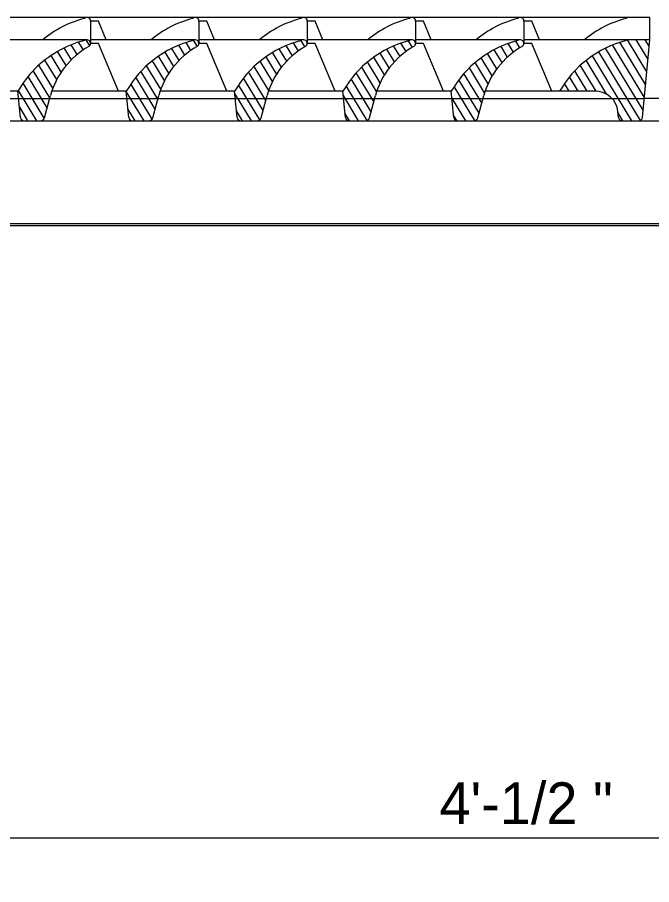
# Model space of a CAD drawing. Extents: x 0.9 to 8.1, y 0.4 to 10.5.
# Drawn here: x 1.927 to 2.656, y 6.36 to 7.357 of the extents above; entities that cross this region are included whole.
import ezdxf

# ---------------------------------------------------------------- set-up
doc = ezdxf.new("R2010")
doc.units = 0
for name, color, linetype in [('DETL-DIMS', 7, 'Continuous'), ('DETL-LINE', 7, 'Continuous'), ('DETL-NOTE', 7, 'Continuous')]:
    doc.layers.add(name, color=color, linetype=linetype)

msp = doc.modelspace()

# ---------------------------------------------------------------- linework, layer by layer
at = {"layer": 'DETL-DIMS'}
msp.add_line((1.8254, 6.41382), (3.48103, 6.41382), dxfattribs=at)
at = {"layer": 'DETL-LINE'}
for p, q in [((2.62959, 7.35673), (1.88268, 7.35673)), ((2.0205, 7.35249), (2.01161, 7.35249)), ((2.01161, 7.35249), (2.01161, 7.32709)), ((2.02944, 7.33132), (2.0205, 7.35249)), ((2.14499, 7.35249), (2.13609, 7.35249)), ((2.13609, 7.35249), (2.13609, 7.32709)), ((2.15392, 7.33132), (2.14499, 7.35249)), ((2.26947, 7.35249), (2.26058, 7.35249)), ((2.26058, 7.35249), (2.26058, 7.32709)), ((2.27841, 7.33132), (2.26947, 7.35249)), ((2.39396, 7.35249), (2.38506, 7.35249)), ((2.38506, 7.35249), (2.38506, 7.32709)), ((2.40289, 7.33132), (2.39396, 7.35249)), ((2.51844, 7.35249), (2.50955, 7.35249)), ((2.50955, 7.35249), (2.50955, 7.32709)), ((2.52737, 7.33132), (2.51844, 7.35249)), ((2.65404, 7.35673), (2.62959, 7.35673)), ((2.65404, 7.33132), (2.65404, 7.35673)), ((2.00716, 7.33132), (1.88713, 7.33132)), ((2.01058, 7.32438), (2.00641, 7.33126)), ((2.13165, 7.33132), (2.01161, 7.33132)), ((2.13423, 7.32364), (2.12981, 7.33094)), ((2.25613, 7.33132), (2.13609, 7.33132)), ((2.25778, 7.32308), (2.25335, 7.33039)), ((2.38062, 7.33132), (2.26058, 7.33132)), ((2.38132, 7.32252), (2.37674, 7.33009)), ((2.5051, 7.33132), (2.38506, 7.33132)), ((2.50488, 7.32196), (2.50013, 7.32978)), ((2.62959, 7.33132), (2.50955, 7.33132)), ((2.65065, 7.29446), (2.6284, 7.33117)), ((2.65404, 7.33132), (2.62959, 7.33132)), ((2.652, 7.30917), (2.63858, 7.33132)), ((2.64583, 7.242), (2.65404, 7.33132)), ((2.65336, 7.32388), (2.64885, 7.33132)), ((1.98954, 7.30827), (1.98133, 7.32181)), ((1.99617, 7.31426), (1.98942, 7.3254)), ((2.00323, 7.31955), (1.99784, 7.32846)), ((2.0205, 7.32709), (2.01161, 7.32709)), ((2.04373, 7.27204), (2.0205, 7.32709)), ((2.11323, 7.30747), (2.10484, 7.32132)), ((2.11981, 7.31356), (2.11288, 7.32498)), ((2.12682, 7.31893), (2.12126, 7.32811)), ((2.14499, 7.32709), (2.13609, 7.32709)), ((2.16822, 7.27204), (2.14499, 7.32709)), ((2.23693, 7.30666), (2.22834, 7.32083)), ((2.24345, 7.31284), (2.23635, 7.32456)), ((2.25041, 7.3183), (2.24468, 7.32775)), ((2.26947, 7.32709), (2.26058, 7.32709)), ((2.2927, 7.27204), (2.26947, 7.32709)), ((2.36064, 7.30584), (2.35185, 7.32033)), ((2.3671, 7.31211), (2.35982, 7.32412)), ((2.37401, 7.31766), (2.36811, 7.32738)), ((2.39396, 7.32709), (2.38506, 7.32709)), ((2.41718, 7.27204), (2.39396, 7.32709)), ((2.48435, 7.30501), (2.47537, 7.31982)), ((2.49076, 7.31137), (2.4833, 7.32368)), ((2.49761, 7.31701), (2.49155, 7.327)), ((2.51844, 7.32709), (2.50955, 7.32709)), ((2.54167, 7.27204), (2.51844, 7.32709)), ((2.6466, 7.25034), (2.60339, 7.32163)), ((2.64795, 7.26505), (2.61146, 7.32524)), ((2.6493, 7.27976), (2.61986, 7.32833)), ((1.9777, 7.29393), (1.96611, 7.31304)), ((1.98337, 7.30151), (1.97356, 7.31769)), ((2.10152, 7.29292), (2.08969, 7.31243)), ((2.10712, 7.30062), (2.0971, 7.31714)), ((2.22535, 7.2919), (2.21328, 7.3118)), ((2.23088, 7.29971), (2.22065, 7.31658)), ((2.34918, 7.29086), (2.33687, 7.31117)), ((2.35464, 7.29879), (2.3442, 7.31602)), ((2.47303, 7.28981), (2.46046, 7.31053)), ((2.47842, 7.29785), (2.46776, 7.31544)), ((2.63346, 7.23815), (2.58819, 7.31281)), ((2.64345, 7.23861), (2.59563, 7.31748)), ((1.96823, 7.27568), (1.95218, 7.30214)), ((1.97261, 7.28538), (1.95898, 7.30787)), ((2.09223, 7.27437), (2.07585, 7.30139)), ((2.09651, 7.28424), (2.0826, 7.30718)), ((2.21624, 7.27305), (2.19952, 7.30063)), ((2.22042, 7.28309), (2.20623, 7.3065)), ((2.34027, 7.27169), (2.32319, 7.29987)), ((2.34434, 7.28191), (2.32986, 7.3058)), ((2.46431, 7.27032), (2.44687, 7.29909)), ((2.46827, 7.28072), (2.4535, 7.30509)), ((2.59238, 7.27204), (2.5743, 7.30186)), ((2.60488, 7.26835), (2.58108, 7.30761)), ((1.96473, 7.26451), (1.94573, 7.29585)), ((2.08882, 7.26306), (2.06944, 7.29503)), ((2.21291, 7.2616), (2.19315, 7.29419)), ((2.337, 7.26015), (2.31687, 7.29335)), ((2.46109, 7.2587), (2.4406, 7.2925)), ((2.58209, 7.27207), (2.56786, 7.29554)), ((1.95837, 7.24113), (1.93397, 7.28139)), ((1.96155, 7.25282), (1.93965, 7.28895)), ((2.08227, 7.23999), (2.05777, 7.2804)), ((2.08564, 7.25136), (2.0634, 7.28805)), ((2.20597, 7.23917), (2.18159, 7.27939)), ((2.20973, 7.24991), (2.18717, 7.28713)), ((2.33382, 7.24846), (2.31093, 7.28621)), ((2.45791, 7.247), (2.43471, 7.28527)), ((2.56157, 7.27205), (2.55613, 7.28102)), ((2.57183, 7.27206), (2.5618, 7.28861)), ((1.92814, 7.27204), (1.84244, 7.27204)), ((1.93089, 7.24203), (1.92814, 7.27204)), ((1.9499, 7.23817), (1.92873, 7.27309)), ((2.05262, 7.27204), (1.96693, 7.27204)), ((2.05538, 7.24203), (2.05262, 7.27204)), ((2.07311, 7.23817), (2.05263, 7.27194)), ((2.17711, 7.27204), (2.09141, 7.27204)), ((2.17986, 7.24203), (2.17711, 7.27204)), ((2.19632, 7.23817), (2.17734, 7.26946)), ((2.30159, 7.27204), (2.2159, 7.27204)), ((2.30435, 7.24203), (2.30159, 7.27204)), ((2.32953, 7.23859), (2.30541, 7.27838)), ((2.42608, 7.27204), (2.34038, 7.27204)), ((2.42883, 7.24203), (2.42608, 7.27204)), ((2.45295, 7.23825), (2.42924, 7.27736)), ((2.55056, 7.27204), (2.46487, 7.27204)), ((2.59097, 7.27207), (2.55056, 7.27204)), ((2.55131, 7.27204), (2.55092, 7.27268)), ((1.83998, 7.26354), (1.92892, 7.26354)), ((1.92892, 7.26354), (1.96446, 7.26354)), ((1.95843, 7.24134), (1.96544, 7.26712)), ((1.96446, 7.26354), (2.0534, 7.26354)), ((2.0534, 7.26354), (2.08895, 7.26354)), ((2.08292, 7.24134), (2.08992, 7.26712)), ((2.08895, 7.26354), (2.17789, 7.26354)), ((2.17789, 7.26354), (2.21343, 7.26354)), ((2.2074, 7.24134), (2.21441, 7.26712)), ((2.21343, 7.26354), (2.30237, 7.26354)), ((2.31952, 7.23817), (2.30206, 7.26698)), ((2.30237, 7.26354), (2.33792, 7.26354)), ((2.33189, 7.24134), (2.33889, 7.26712)), ((2.33792, 7.26354), (2.42686, 7.26354)), ((2.44273, 7.23817), (2.42677, 7.2645)), ((2.42686, 7.26354), (2.4624, 7.26354)), ((2.45637, 7.24134), (2.46338, 7.26712)), ((2.4624, 7.26354), (2.61089, 7.26357)), ((2.61089, 7.26357), (2.64781, 7.26354)), ((2.66471, 7.26354), (2.64781, 7.26354)), ((1.93963, 7.23817), (1.92975, 7.25446)), ((2.06284, 7.23817), (2.05447, 7.25198)), ((2.18605, 7.23817), (2.17918, 7.2495)), ((2.30926, 7.23817), (2.30389, 7.24702)), ((2.43242, 7.23824), (2.4286, 7.24453)), ((2.61817, 7.24203), (2.61755, 7.24888)), ((2.62318, 7.23816), (2.6177, 7.2472)), ((1.84934, 7.23813), (3.46319, 7.23813)), ((1.93532, 7.23817), (1.95413, 7.23817)), ((2.05981, 7.23817), (2.07861, 7.23817)), ((2.18429, 7.23817), (2.2031, 7.23817)), ((2.30878, 7.23817), (2.32758, 7.23817)), ((2.43326, 7.23817), (2.45207, 7.23817)), ((2.6226, 7.23817), (2.6414, 7.23813)), ((3.52962, 7.11961), (1.78291, 7.11961))]:
    msp.add_line(p, q, dxfattribs=at)
msp.add_lwpolyline([(1.50664, 6.30683), (1.50664, 7.11752), (3.76982, 7.11752), (3.76982, 5.37673), (1.50664, 5.37673), (1.50664, 5.58877)], dxfattribs=at)
for centre, major_axis, start_param, end_param in [((2.03796, 7.24163), (0.12448, 0), 1.843967, 2.283635), ((2.00716, 7.35249), (0.00445, 0), 0, 2.247685), ((2.16245, 7.24163), (0.12448, 0), 1.843967, 2.283635), ((2.13165, 7.35249), (0.00445, 0), 0, 2.247685), ((2.28693, 7.24163), (0.12448, 0), 1.843967, 2.283635), ((2.25613, 7.35249), (0.00445, 0), 0, 2.247685), ((2.41142, 7.24163), (0.12448, 0), 1.843967, 2.283635), ((2.38062, 7.35249), (0.00445, 0), 0, 2.247685), ((2.5359, 7.24163), (0.12448, 0), 1.843967, 2.283635), ((2.5051, 7.35249), (0.00445, 0), 0, 2.247685), ((2.66039, 7.24163), (0.12448, 0), 1.843967, 2.283635), ((2.62959, 7.35249), (0.00445, 0), 1.570796, 2.247685), ((2.03796, 7.21623), (0.12448, 0), 1.843967, 2.386879), ((2.00716, 7.32709), (0.00445, 0), 5.256857, 8.53087), ((2.16245, 7.21623), (0.12448, 0), 1.843967, 2.651402), ((2.13165, 7.32709), (0.00445, 0), 5.256857, 8.53087), ((2.28693, 7.21623), (0.12448, 0), 1.843967, 2.651402), ((2.25613, 7.32709), (0.00445, 0), 5.256857, 8.53087), ((2.41142, 7.21623), (0.12448, 0), 1.843967, 2.651402), ((2.38062, 7.32709), (0.00445, 0), 1.128272, 2.247685), ((2.38062, 7.32709), (0.00445, 0), 5.256857, 7.411457), ((2.5359, 7.21623), (0.12448, 0), 1.843967, 2.651402), ((2.5051, 7.32709), (0.00445, 0), 5.256857, 8.53087), ((2.66039, 7.21623), (0.12448, 0), 1.843967, 2.651402), ((2.62959, 7.32709), (0.00445, 0), 1.570796, 2.247685), ((2.06013, 7.24378), (0.09781, 0), 2.115265, 2.888349), ((2.18461, 7.24378), (0.09781, 0), 2.115265, 2.888349), ((2.3091, 7.24378), (0.09781, 0), 2.115265, 2.888349), ((2.43358, 7.24378), (0.09781, 0), 2.115265, 2.888349), ((2.55807, 7.24378), (0.09781, 0), 2.115265, 2.888349), ((2.03796, 7.21623), (0.12448, 0), 2.386879, 2.651402), ((2.59097, 7.24667), (0.02668, 0), 0.087266, 1.570796), ((1.93532, 7.2424), (0.00445, 0), 3.228859, 4.712348), ((1.95413, 7.2424), (0.00445, 0), 4.712348, 6.029942), ((2.05981, 7.2424), (0.00445, 0), 3.228859, 4.712348), ((2.07861, 7.2424), (0.00445, 0), 4.712348, 6.029942), ((2.18429, 7.2424), (0.00445, 0), 3.228859, 4.712348), ((2.2031, 7.2424), (0.00445, 0), 4.712348, 6.029942), ((2.30878, 7.2424), (0.00445, 0), 3.228859, 4.712348), ((2.32758, 7.2424), (0.00445, 0), 4.712348, 6.029942), ((2.43326, 7.2424), (0.00445, 0), 3.228859, 4.712348), ((2.45207, 7.2424), (0.00445, 0), 4.712348, 6.029942), ((2.6226, 7.2424), (0.00445, 0), 3.228859, 4.712348), ((2.6414, 7.24237), (0.00445, 0), 4.712348, 6.195919)]:
    msp.add_ellipse(centre, major_axis=major_axis, ratio=0.952381, start_param=start_param, end_param=end_param, dxfattribs=at)

# ---------------------------------------------------------------- texts
at = {"layer": 'DETL-NOTE'}
msp.add_text('4\'-1/2 "', height=0.048, dxfattribs=at).set_placement((2.41247, 6.4295))

doc.saveas('drawing.dxf')
